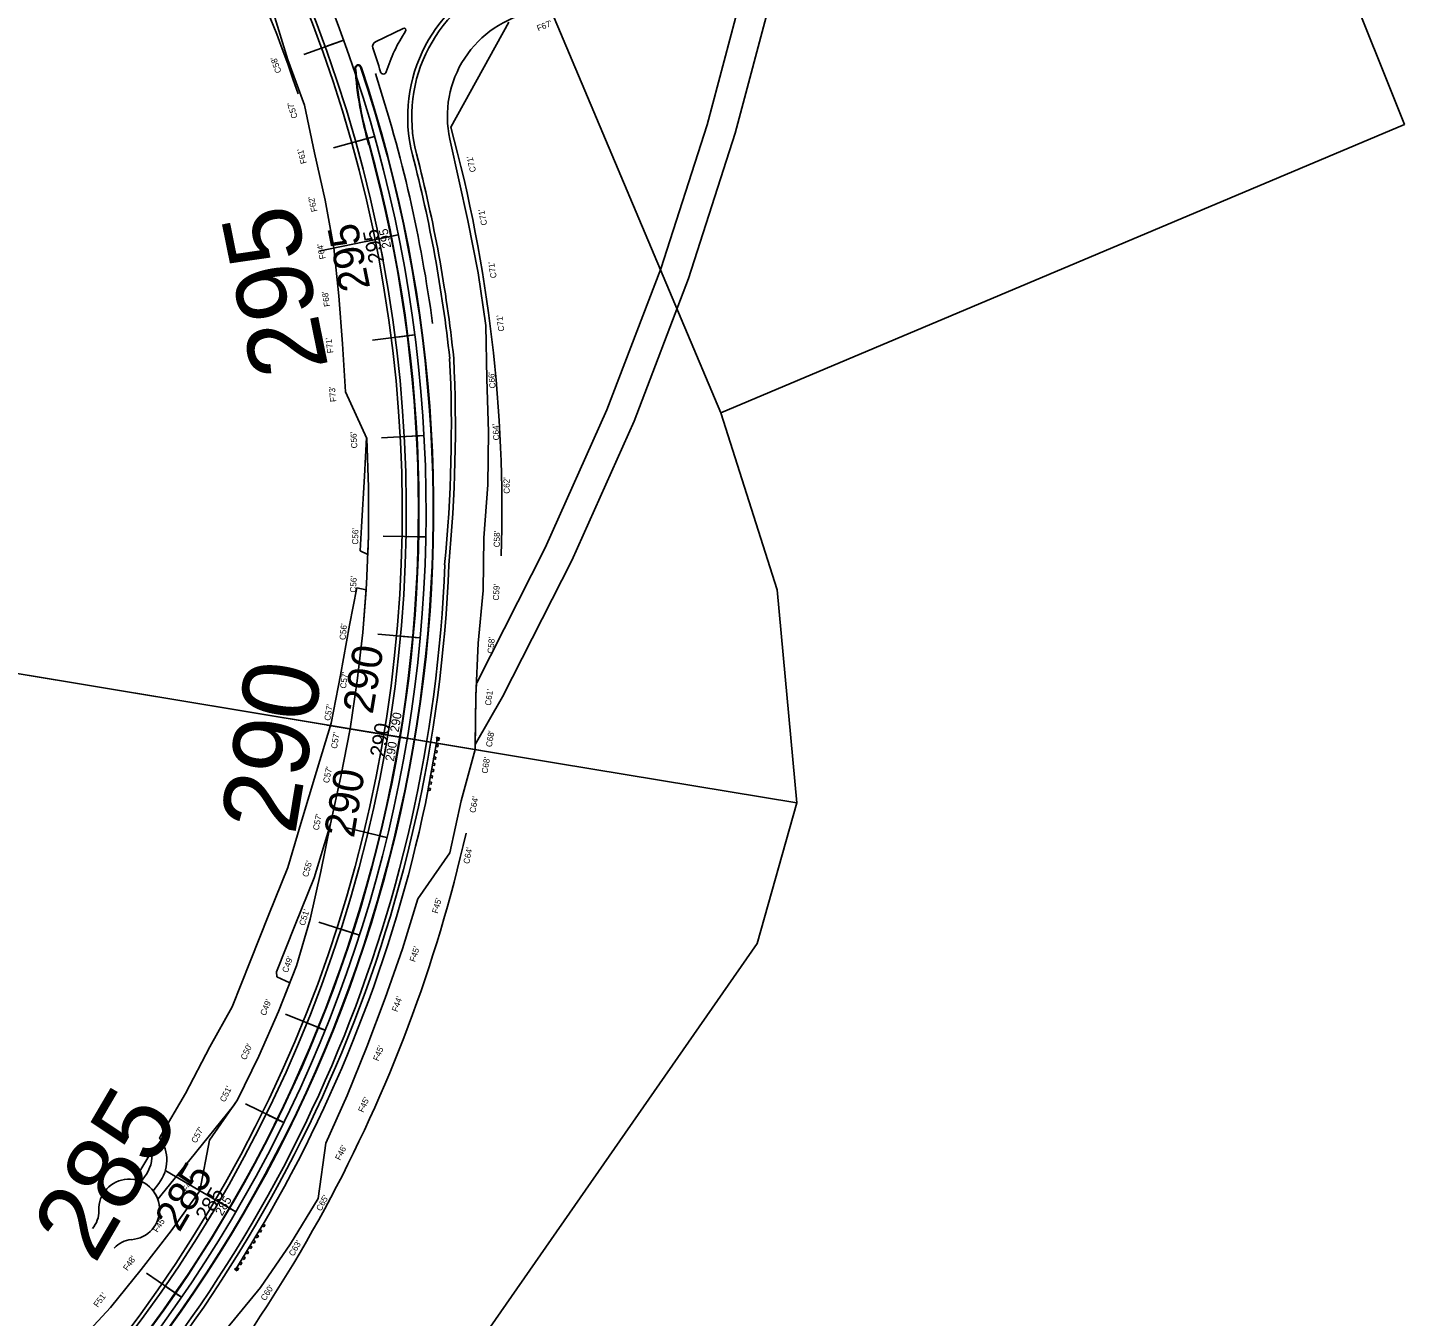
# Model space of a CAD drawing. Extents: x 2358865 to 2362945, y 393485 to 404880.
# Drawn here: x 2361585 to 2362945, y 400160 to 401432 of the extents above; entities that cross this region are included whole.
import ezdxf

# ---------------------------------------------------------------- set-up
doc = ezdxf.new("R2010")
doc.units = 0
for name, color, linetype in [('CL', 7, 'Continuous'), ('Level 11', 7, 'Continuous'), ('Level 12', 7, 'Continuous'), ('Level 19', 7, 'Continuous'), ('Level 25', 7, 'Continuous'), ('Level 27', 7, 'Continuous'), ('Level 30', 7, 'Continuous'), ('Level 35', 7, 'Continuous'), ('Level 36', 7, 'Continuous'), ('Level 37', 7, 'Continuous'), ('Level 39', 7, 'Continuous'), ('Level 41', 7, 'Continuous'), ('Level 48', 7, 'Continuous'), ('Level 50', 7, 'Continuous'), ('Level 51', 7, 'Continuous'), ('Level 52', 7, 'Continuous'), ('Level 53', 7, 'Continuous'), ('Level 61', 7, 'Continuous'), ('Level 63', 7, 'Continuous')]:
    doc.layers.add(name, color=color, linetype=linetype)

msp = doc.modelspace()

# ---------------------------------------------------------------- linework, layer by layer
at = {"layer": 'CL'}
msp.add_arc((2360608.6, 400955.3), 1370, 315.7519, 87.327, dxfattribs=at)
at = {"layer": 'Level 11'}
for centre, radius, start, end in [((2360608.6, 400955.3), 1346.5, 319.7207, 43.5046), ((2362110.5, 401344.4), 146, 109.9549, 194.5241), ((2360608.6, 400955.3), 1405.5, 6.1559, 14.5241), ((2360610.5, 401037.4), 1397.1, 354.4217, 2.8149), ((2360608.6, 400955.3), 1393.5, 315.7519, 357.7915)]:
    msp.add_arc(centre, radius, start, end, dxfattribs=at)
at = {"layer": 'Level 12'}
for p, q in [((2361989.6, 400729.8), (2361980.8, 400680.6)), ((2361989.6, 400729.8), (2361980.8, 400680.6)), ((2361989.6, 400729.8), (2361988.8, 400731.8)), ((2361991.9, 400731.2), (2361988.8, 400731.8)), ((2361991.7, 400731), (2361988.9, 400731.5)), ((2361990.5, 400729.6), (2361991.9, 400731.2)), ((2361791.4, 400207.3), (2361817.3, 400250)), ((2361791.4, 400207.3), (2361817.3, 400250)), ((2361791.4, 400207.3), (2361789.5, 400206.3)), ((2361792.2, 400204.7), (2361789.5, 400206.3)), ((2361792.2, 400205), (2361789.8, 400206.5)), ((2361792.2, 400206.8), (2361792.2, 400204.7))]:
    msp.add_line(p, q, dxfattribs=at)
for points in [[(2361990.6, 400724.3), (2361990.3, 400722.3), (2361988.3, 400722.7), (2361988.6, 400724.6)], [(2361991.7, 400730.4), (2361991.4, 400728.5), (2361989.4, 400728.8), (2361989.7, 400730.8)], [(2361988.4, 400712), (2361988.1, 400710), (2361986.1, 400710.4), (2361986.5, 400712.3)], [(2361989.5, 400718.1), (2361989.2, 400716.2), (2361987.2, 400716.5), (2361987.5, 400718.5)], [(2361986.2, 400699.7), (2361985.9, 400697.7), (2361983.9, 400698), (2361984.3, 400700)], [(2361987.3, 400705.8), (2361987, 400703.8), (2361985, 400704.2), (2361985.4, 400706.2)], [(2361984.1, 400687.4), (2361983.7, 400685.4), (2361981.7, 400685.7), (2361982.1, 400687.7)], [(2361985.1, 400693.5), (2361984.8, 400691.5), (2361982.8, 400691.9), (2361983.2, 400693.9)], [(2361983, 400681.2), (2361982.6, 400679.2), (2361980.6, 400679.6), (2361981, 400681.5)], [(2361818.5, 400248.2), (2361819.6, 400249.9), (2361817.9, 400250.9), (2361816.8, 400249.2)], [(2361812, 400237.5), (2361813.1, 400239.2), (2361811.4, 400240.2), (2361810.3, 400238.5)], [(2361815.3, 400242.8), (2361816.3, 400244.5), (2361814.6, 400245.6), (2361813.6, 400243.9)], [(2361802.3, 400221.5), (2361803.3, 400223.2), (2361801.6, 400224.2), (2361800.6, 400222.5)], [(2361805.6, 400226.8), (2361806.6, 400228.5), (2361804.9, 400229.5), (2361803.8, 400227.8)], [(2361808.8, 400232.1), (2361809.8, 400233.8), (2361808.1, 400234.9), (2361807.1, 400233.2)], [(2361792.6, 400205.4), (2361793.6, 400207.1), (2361791.9, 400208.2), (2361790.9, 400206.5)], [(2361795.8, 400210.8), (2361796.9, 400212.5), (2361795.1, 400213.5), (2361794.1, 400211.8)], [(2361799.1, 400216.1), (2361800.1, 400217.8), (2361798.4, 400218.9), (2361797.4, 400217.1)]]:
    msp.add_lwpolyline(points, close=True, dxfattribs=at)
msp.add_arc((2360608.6, 400955.3), 1399.5, 329.7402, 348.675, dxfattribs=at)
at = {"layer": 'Level 19'}
for centre, radius, start, end in [((2360608.6, 400955.3), 1350.5, 319.7207, 43.5046), ((2362110.5, 401344.4), 150, 109.9549, 194.5241), ((2360608.6, 400955.3), 1401.5, 6.1607, 14.5241), ((2360610.5, 401037.4), 1393.1, 354.4168, 2.8101), ((2360608.6, 400955.3), 1389.5, 315.7519, 357.7964), ((2361685.5, 400265.4), 30, 274.2043, 182.3952), ((2361630.5, 400263.1), 25, 318.2997, 2.3952), ((2361689.5, 400210.6), 25, 94.2043, 138.2997)]:
    msp.add_arc(centre, radius, start, end, dxfattribs=at)
at = {"layer": 'Level 25'}
for p, q in [((2361897.3, 401420.1), (2361892.6, 401418.4)), ((2361927.8, 401324.9), (2361923, 401323.5)), ((2361951.2, 401227.7), (2361943.4, 401226.1)), ((2361967.5, 401129), (2361962.5, 401128.4)), ((2361976.5, 401029.5), (2361971.6, 401029.2)), ((2361978.3, 400929.5), (2361973.3, 400929.6)), ((2361972.8, 400829.7), (2361967.8, 400830.1)), ((2361960, 400730.5), (2361952.1, 400731.8)), ((2361940, 400632.6), (2361935.1, 400633.8)), ((2361912.9, 400536.3), (2361908.1, 400537.9)), ((2361878.9, 400442.3), (2361874.2, 400444.2)), ((2361838.1, 400351.1), (2361833.6, 400353.3)), ((2361790.7, 400263), (2361783.8, 400267)), ((2361737.1, 400178.6), (2361733, 400181.5))]:
    msp.add_line(p, q, dxfattribs=at)
at = {"layer": 'Level 27'}
msp.add_line((2362003, 401334.2), (2362060.5, 401437.7), dxfattribs=at)
for radius, start, end in [(1310, 18.3189, 61.6527), (1445, 358.239, 15.2014), (1445, 315.7519, 347.2778)]:
    msp.add_arc((2360608.6, 400955.3), radius, start, end, dxfattribs=at)
at = {"layer": 'Level 30'}
for p, q in [((2361897.3, 401420.1), (2361889.3, 401417.2)), ((2361927.8, 401324.9), (2361919.6, 401322.6)), ((2361951.2, 401227.7), (2361935.5, 401224.5)), ((2361967.5, 401129), (2361959.1, 401128)), ((2361976.5, 401029.5), (2361968.1, 401029)), ((2361978.3, 400929.5), (2361969.8, 400929.7)), ((2361972.8, 400829.7), (2361964.3, 400830.5)), ((2361960, 400730.5), (2361944.2, 400733.2)), ((2361940, 400632.6), (2361931.7, 400634.6)), ((2361912.9, 400536.3), (2361904.8, 400538.9)), ((2361878.9, 400442.3), (2361871, 400445.5)), ((2361838.1, 400351.1), (2361830.5, 400354.8)), ((2361790.7, 400263), (2361776.9, 400271.1)), ((2361737.1, 400178.6), (2361730.1, 400183.4))]:
    msp.add_line(p, q, dxfattribs=at)
at = {"layer": 'Level 35'}
msp.add_line((2361928.7, 401418.5), (2361955.9, 401431.7), dxfattribs=at)
for centre, radius, start, end in [((2361930.9, 401414), 5, 115.9165, 197.9963), ((2360604.7, 400983.2), 1389.5, 16.9658, 17.9963)]:
    msp.add_arc(centre, radius, start, end, dxfattribs=at)
at = {"layer": 'Level 36'}
msp.add_arc((2360608, 400954.8), 1389.5, 7.6672, 18.1225, dxfattribs=at)
at = {"layer": 'Level 37'}
for centre, radius, start, end in [((2361956.8, 401429.9), 2, 326.2257, 115.9165), ((2362085.3, 401344), 152.6, 146.2257, 162.9914), ((2360608.6, 400955.3), 1377, 318.2817, 18.5519), ((2360608.6, 400955.3), 1377.5, 318.2817, 18.5519), ((2361911.6, 401392.6), 3, 18.5667, 183.8666), ((2362257.6, 401416.2), 349.8, 183.8875, 196.5259), ((2361911.6, 401392.6), 2.5, 18.5667, 183.8666), ((2362257.6, 401416.2), 349.3, 183.8867, 196.5267), ((2361936.5, 401389.5), 3, 196.9658, 342.9914), ((2360608.6, 400955.3), 1362.5, 318.2817, 15.3784), ((2360608.6, 400955.3), 1363, 318.2817, 15.3784)]:
    msp.add_arc(centre, radius, start, end, dxfattribs=at)
at = {"layer": 'Level 39'}
for p, q in [((2361897.3, 401420.1), (2361881.3, 401414.3)), ((2361927.8, 401324.9), (2361911.4, 401320.3)), ((2361951.2, 401227.7), (2361919.8, 401221.3)), ((2361967.5, 401129), (2361950.6, 401126.9)), ((2361976.5, 401029.5), (2361959.6, 401028.6)), ((2361978.3, 400929.5), (2361961.3, 400929.8)), ((2361972.8, 400829.7), (2361955.9, 400831.3)), ((2361960, 400730.5), (2361928.4, 400735.8)), ((2361940, 400632.6), (2361923.5, 400636.6)), ((2361912.9, 400536.3), (2361896.7, 400541.5)), ((2361878.9, 400442.3), (2361863.1, 400448.7)), ((2361838.1, 400351.1), (2361822.8, 400358.6)), ((2361790.7, 400263), (2361763.1, 400279.2)), ((2361737.1, 400178.6), (2361723.1, 400188.3))]:
    msp.add_line(p, q, dxfattribs=at)
at = {"layer": 'Level 41'}
for p, q in [((2361897.3, 401420.1), (2361857.8, 401405.9)), ((2361927.8, 401324.9), (2361887.3, 401313.6)), ((2361951.2, 401227.7), (2361872.8, 401211.8)), ((2361967.5, 401129), (2361925.8, 401123.7)), ((2361976.5, 401029.5), (2361934.6, 401027.2)), ((2361978.3, 400929.5), (2361936.3, 400930.3)), ((2361972.8, 400829.7), (2361931, 400833.5)), ((2361960, 400730.5), (2361881.1, 400743.7)), ((2361940, 400632.6), (2361899.2, 400642.5)), ((2361912.9, 400536.3), (2361872.9, 400549.2)), ((2361878.9, 400442.3), (2361839.9, 400458.1)), ((2361838.1, 400351.1), (2361800.4, 400369.6)), ((2361790.7, 400263), (2361721.7, 400303.4)), ((2361737.1, 400178.6), (2361702.5, 400202.4))]:
    msp.add_line(p, q, dxfattribs=at)
at = {"layer": 'Level 48'}
for centre, radius, start, end in [((2360608.6, 400955.3), 1377, 318.2817, 18.5519), ((2361911.6, 401392.6), 2.5, 18.5667, 183.8666), ((2362257.6, 401416.2), 349.3, 183.8867, 196.5267), ((2360608.6, 400955.3), 1363, 318.2817, 15.3784)]:
    msp.add_arc(centre, radius, start, end, dxfattribs=at)
at = {"layer": 'Level 50'}
for p, q in [((2361842.3, 401400.7), (2361828.1, 401446.6)), ((2361858.7, 401355.7), (2361842.3, 401400.7)), ((2362019.8, 401242), (2362002.1, 401322.3)), ((2362030, 401190.4), (2362019.8, 401242)), ((2362037.8, 401138.4), (2362030, 401190.4)), ((2362038.5, 401085.6), (2362037.8, 401138.4)), ((2362040.2, 401033.2), (2362038.5, 401085.6)), ((2361921.8, 400978.7), (2361920.3, 401026.6)), ((2362039.7, 400980.9), (2362040.2, 401033.2)), ((2361921.8, 400930.8), (2361921.8, 400978.7)), ((2362035.6, 400928.7), (2362039.7, 400980.9)), ((2361919.9, 400882.8), (2361921.8, 400930.8)), ((2362035, 400876.5), (2362035.6, 400928.7)), ((2361916.1, 400835.1), (2361919.9, 400882.8)), ((2362030, 400824.6), (2362035, 400876.5)), ((2361910.7, 400787.4), (2361916.1, 400835.1)), ((2362027.8, 400772.4), (2362030, 400824.6)), ((2361903.7, 400740), (2361910.7, 400787.4)), ((2362027, 400719.6), (2362027.8, 400772.4)), ((2361894.4, 400693), (2361903.7, 400740)), ((2362013.4, 400668.8), (2362027, 400719.6)), ((2361884.2, 400646.1), (2361894.4, 400693)), ((2362002.1, 400617.5), (2362013.4, 400668.8)), ((2361874.9, 400599), (2361884.2, 400646.1)), ((2361864.3, 400552), (2361874.9, 400599)), ((2361850.6, 400505.8), (2361864.3, 400552)), ((2361832.8, 400461), (2361850.6, 400505.8)), ((2361813.6, 400416.8), (2361832.8, 400461)), ((2361792.5, 400373.5), (2361813.6, 400416.8)), ((2361764.8, 400333.7), (2361792.5, 400373.5)), ((2361844.7, 400231.5), (2361872.1, 400276.1)), ((2361815.2, 400188.3), (2361844.7, 400231.5))]:
    msp.add_line(p, q, dxfattribs=at)
at = {"layer": 'Level 51'}
for p, q in [((2361879, 401262), (2361868.6, 401308.7)), ((2361887.6, 401215.1), (2361879, 401262)), ((2361892.5, 401167.6), (2361887.6, 401215.1)), ((2361896.1, 401120.2), (2361892.5, 401167.6)), ((2361899.1, 401072.9), (2361896.1, 401120.2)), ((2361955.3, 400522.8), (2361970.6, 400572.2)), ((2361938.3, 400474.1), (2361955.3, 400522.8)), ((2361920.1, 400425.8), (2361938.3, 400474.1)), ((2361900.6, 400378), (2361920.1, 400425.8)), ((2361879.6, 400330.7), (2361900.6, 400378)), ((2361726.9, 400244.3), (2361755.3, 400283.8)), ((2361697.2, 400206), (2361726.9, 400244.3)), ((2361667.1, 400168.4), (2361697.2, 400206)), ((2361634.1, 400133.1), (2361667.1, 400168.4))]:
    msp.add_line(p, q, dxfattribs=at)
at = {"layer": 'Level 52'}
for p, q in [((2361868.6, 401308.7), (2361858.7, 401355.7)), ((2361920.3, 401026.6), (2361899.1, 401072.9)), ((2361970.6, 400572.2), (2362002.1, 400617.5)), ((2361755.3, 400283.8), (2361764.8, 400333.7)), ((2361872.1, 400276.1), (2361879.6, 400330.7)), ((2361781.8, 400147.9), (2361815.2, 400188.3))]:
    msp.add_line(p, q, dxfattribs=at)
msp.add_arc((2362104.7, 401344.9), 105, 101.2996, 192.4245, dxfattribs=at)
at = {"layer": 'Level 61'}
for p, q in [((2362294.4, 401480.5), (2362256.1, 401336.3)), ((2362283.9, 401328.2), (2362322.7, 401473.8)), ((2362256.1, 401336.3), (2362210.4, 401194.2)), ((2362237.8, 401184.6), (2362283.9, 401328.2)), ((2362210.4, 401194.2), (2362157.2, 401055)), ((2362184, 401043.9), (2362237.8, 401184.6)), ((2362157.2, 401055), (2362096.2, 400918.7)), ((2362122.4, 400906.2), (2362184, 401043.9)), ((2361919.9, 401027.5), (2361920.3, 401026.6)), ((2361920.3, 401026.6), (2361921.8, 400978.7)), ((2361915, 400939.6), (2361917.8, 400989.5)), ((2361921.8, 400978.7), (2361921.8, 400930.8)), ((2361913.7, 400915.7), (2361915, 400939.6)), ((2361921.8, 400930.8), (2361921, 400912)), ((2361921, 400912), (2361913.7, 400915.7)), ((2362096.2, 400918.7), (2362028.6, 400785.4)), ((2362054.1, 400771.6), (2362122.4, 400906.2)), ((2361910.2, 400879.3), (2361903.2, 400842.3)), ((2361919.4, 400877.1), (2361910.2, 400879.3)), ((2361916.1, 400835.1), (2361919.4, 400877.1)), ((2361903.2, 400842.3), (2361894, 400793.1)), ((2361910.7, 400787.4), (2361916.1, 400835.1)), ((2361894, 400793.1), (2361885.1, 400745.5)), ((2361903.7, 400740), (2361910.7, 400787.4)), ((2362028.4, 400785.1), (2362027.8, 400772.4)), ((2362028.6, 400785.4), (2362028.4, 400785.1)), ((2362027.8, 400772.4), (2362027.1, 400724.5)), ((2362027.1, 400724.5), (2362054.1, 400771.6)), ((2361885.1, 400745.5), (2361870.6, 400697.7)), ((2361894.4, 400693), (2361903.7, 400740)), ((2361870.6, 400697.7), (2361856.1, 400649.8)), ((2361884.2, 400646.1), (2361894.4, 400693)), ((2361856.1, 400649.8), (2361842, 400603.2)), ((2361882.9, 400641.7), (2361884.1, 400645.6)), ((2361884.1, 400645.6), (2361884.2, 400646.1)), ((2361868, 400592.8), (2361882.9, 400641.7)), ((2361842, 400603.2), (2361823.5, 400556.7)), ((2361849.5, 400546.4), (2361868, 400592.8)), ((2361823.5, 400556.7), (2361805, 400510.3)), ((2361831, 400499.9), (2361849.5, 400546.4)), ((2361805, 400510.3), (2361787.3, 400465.5)), ((2361831.4, 400495.2), (2361831, 400499.9)), ((2361844, 400489.1), (2361831.4, 400495.2)), ((2361832.8, 400461), (2361844, 400489.1)), ((2361787.3, 400465.5), (2361765.2, 400425.8)), ((2361813.6, 400416.8), (2361832.8, 400461)), ((2361765.2, 400425.8), (2361741.2, 400380)), ((2361792.5, 400373.5), (2361813.6, 400416.8)), ((2361741.2, 400380), (2361716.6, 400337.7)), ((2361788.4, 400367.7), (2361792.5, 400373.5)), ((2361745.3, 400314.4), (2361788.4, 400367.7)), ((2361716.6, 400337.7), (2361715.5, 400335.9)), ((2361713.7, 400275.4), (2361745.3, 400314.4)), ((2361691, 400294.9), (2361691, 400294.9)), ((2361697.2, 400293.1), (2361700.7, 400297.6)), ((2361714.7, 400291), (2361709.1, 400283.8))]:
    msp.add_line(p, q, dxfattribs=at)
for points in [[(2361917.8, 400989.5), (2361919.9, 401027.5)], [(2361707.8, 400323), (2361691, 400294.9)]]:
    msp.add_lwpolyline(points, dxfattribs=at)
for centre, radius, start, end in [((2361685.5, 400314), 37.2, 321.8945, 36.1721), ((2361673.6, 400318.8), 34.4, 321.8945, 6.9951), ((2361685.5, 400265.4), 30, 67.026, 79.4052), ((2361685.5, 400265.4), 30, 19.4489, 37.8401)]:
    msp.add_arc(centre, radius, start, end, dxfattribs=at)
at = {"layer": 'Level 63'}
for points in [[(2362461.5, 402543.9), (2361764.4, 402249.8), (2362269.7, 401052), (2362944.6, 401336.8)], [(2361426.4, 402053.5), (2361146.5, 401677.8), (2361146.5, 401677.8), (2361497.4, 400807.4), (2361959.6, 400730.7), (2361959.6, 400730.7), (2362107.5, 400706.2), (2362344.7, 400666.9), (2362325.2, 400877.2), (2362269.7, 401052), (2361764.4, 402249.8), (2361644.3, 402346.2), (2361515.9, 402173.8)], [(2361523.4, 400803.1), (2360833.3, 399804.1), (2361123.9, 399521), (2361123.9, 399521), (2361410.5, 399241.9), (2362305.6, 400527.9), (2362344.7, 400666.9), (2362107.5, 400706.2), (2362028.4, 400719.3)]]:
    msp.add_lwpolyline(points, close=True, dxfattribs=at)

# ---------------------------------------------------------------- texts
at = {"layer": 'Level 25'}
for s, rotation, p in [('295', 101.4666, (2361944.3, 401215.4)), ('290', 80.5558, (2361951.5, 400736.2)), ('290', 80.5558, (2361946.8, 400707.4)), ('285', 59.6449, (2361777.3, 400258.4))]:
    msp.add_text(s, height=8.75, rotation=rotation, dxfattribs=at).set_placement(p)
at = {"layer": 'Level 30'}
for s, rotation, p in [('295', 101.4666, (2361937.4, 401201.6)), ('290', 80.5558, (2361937.8, 400711.3)), ('285', 59.6449, (2361762.9, 400252.5))]:
    msp.add_text(s, height=15, rotation=rotation, dxfattribs=at).set_placement(p)
at = {"layer": 'Level 39'}
for s, rotation, p in [('295', 101.4666, (2361923.6, 401175.5)), ('290', 80.5558, (2361925.9, 400753.7)), ('290', 80.5558, (2361907.3, 400631.5)), ('285', 59.6449, (2361735.1, 400242))]:
    msp.add_text(s, height=30, rotation=rotation, dxfattribs=at).set_placement(p)
at = {"layer": 'Level 41'}
for s, rotation, p in [('295', 101.4666, (2361882.3, 401097)), ('290', 80.5558, (2361849.2, 400634.2)), ('285', 59.6449, (2361651.5, 400210.3))]:
    msp.add_text(s, height=75, rotation=rotation, dxfattribs=at).set_placement(p)
at = {"layer": 'Level 53'}
for s, rotation, p in [("F67'", 22.7542, (2362089.5, 401428.6)), ("C58'", 109.8494, (2361836, 401388.7)), ("C57'", 107.7573, (2361852, 401343.8)), ("F61'", 105.6651, (2361861, 401298.8)), ("C71'", 103.573, (2362028.1, 401290.4)), ("F62'", 103.573, (2361871.4, 401251.2)), ("C71'", 101.4809, (2362039.1, 401237.8)), ("F64'", 101.4809, (2361879.6, 401204.4)), ("C71'", 99.3889, (2362048.4, 401185.5)), ("F68'", 99.3889, (2361884, 401157.3)), ("C71'", 97.2968, (2362056, 401132.8)), ("F71'", 97.2968, (2361887.2, 401111.3)), ("C66'", 95.2048, (2362047.4, 401076.4)), ("F73'", 95.2048, (2361890, 401063)), ("C64'", 93.1128, (2362051, 401025)), ("C56'", 93.1128, (2361910.8, 401017.1)), ("C62'", 91.0209, (2362061.3, 400972.2)), ("C56'", 88.929, (2361911.6, 400921.9)), ("C58'", 88.929, (2362051.4, 400919.2)), ("C56'", 86.8371, (2361909.4, 400874.4)), ("C59'", 86.8371, (2362050.5, 400866.6)), ("C56'", 84.7452, (2361899.1, 400827.5)), ("C58'", 84.7452, (2362045.1, 400814)), ("C57'", 82.6534, (2361899.6, 400779.5)), ("C61'", 82.6534, (2362042.7, 400762.6)), ("C57'", 80.5616, (2361883.9, 400747.6)), ("C57'", 80.5616, (2361890.6, 400720)), ("C68'", 80.5616, (2362043.5, 400721.6)), ("C68'", 80.5616, (2362039.2, 400695.5)), ("C57'", 78.4699, (2361882.7, 400686)), ("C64'", 78.4699, (2362027.2, 400656.6)), ("C57'", 78.4699, (2361872.6, 400639.4)), ("C64'", 78.4699, (2362021.2, 400606.2)), ("C55'", 74.2865, (2361862, 400593.1)), ("C51'", 72.1948, (2361858.7, 400545.1)), ("F45'", 74.2865, (2361990.1, 400557.2)), ("F45'", 72.1948, (2361967.8, 400509.3)), ("C49'", 70.1032, (2361841.9, 400498.6)), ("C49'", 68.0117, (2361820.1, 400456.2)), ("F44'", 70.1032, (2361950.2, 400460)), ("C50'", 65.9202, (2361800.7, 400412.5)), ("F45'", 68.0117, (2361931.6, 400411.4)), ("C51'", 63.8287, (2361780, 400370.8)), ("F45'", 65.9202, (2361916.7, 400360.6)), ("C57'", 61.7372, (2361751.6, 400330.3)), ("F46'", 63.8287, (2361893.9, 400313.3)), ("F41'", 59.6459, (2361742.7, 400282.1)), ("C65'", 61.7372, (2361875, 400263.2)), ("F45'", 57.5545, (2361713.6, 400242.1)), ("C63'", 59.6459, (2361847.8, 400218.6)), ("F48'", 55.4632, (2361683.9, 400204.3)), ("F51'", 53.3719, (2361654.5, 400168.2)), ("C60'", 57.5545, (2361819.9, 400174.7))]:
    msp.add_text(s, height=6, rotation=rotation, dxfattribs=at).set_placement(p)

doc.saveas('drawing.dxf')
